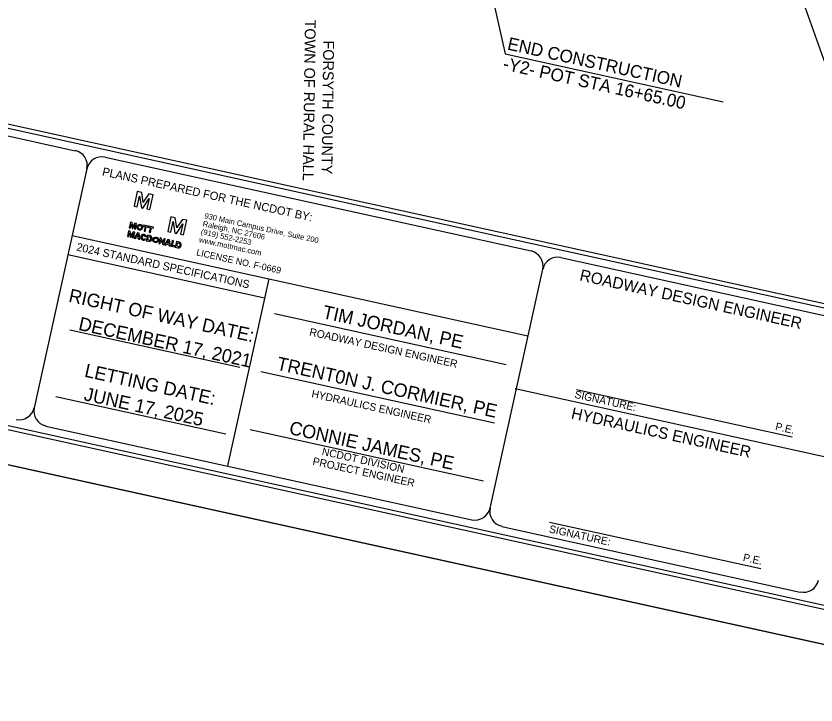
# Model space of a CAD drawing. Extents: x 1609449 to 1623942, y 894240 to 902860.
# Drawn here: x 1618272 to 1621409, y 894240 to 896944 of the extents above; entities that cross this region are included whole.
import ezdxf

# ---------------------------------------------------------------- set-up
doc = ezdxf.new("R2010")
doc.units = 0
for name, color, linetype in [('Old_Level_2', 7, 'Continuous'), ('Prop Horizontal Alignment Station Label', 7, 'Continuous'), ('Scratch_Level_0', 7, 'Continuous'), ('Scratch_Level_1', 7, 'Continuous'), ('Sheet Cutting Line CELL', 7, 'Continuous'), ('Sheet Data Field CELL', 7, 'Continuous'), ('Sheet Plot Border Inside CELL', 7, 'Continuous'), ('Sheet Plot Border Outside CELL', 7, 'Continuous'), ('Sheet Title CELL', 7, 'Continuous')]:
    doc.layers.add(name, color=color, linetype=linetype)

msp = doc.modelspace()

# ---------------------------------------------------------------- linework, layer by layer
at = {"layer": 'Old_Level_2'}
for p, q in [((1618747.5, 896255.9), (1618734.8, 896198.2)), ((1618764.6, 896252.1), (1618747.5, 896255.9)), ((1618770.7, 896213.4), (1618764.6, 896252.1)), ((1618746.9, 896195.5), (1618756.1, 896237)), ((1618756.1, 896237), (1618756.2, 896237)), ((1618756.2, 896237), (1618763.3, 896191.9)), ((1618768.6, 896190.8), (1618794, 896228.8)), ((1618792.8, 896245.9), (1618771, 896213.4)), ((1618794.2, 896228.8), (1618785, 896187.2)), ((1618809.9, 896242.1), (1618792.8, 896245.9)), ((1618794, 896228.8), (1618794.2, 896228.8)), ((1618797.2, 896184.5), (1618809.9, 896242.1)), ((1618734.8, 896198.2), (1618746.9, 896195.5)), ((1618763.3, 896191.9), (1618768.6, 896190.8)), ((1618770.5, 896212.9), (1618770.7, 896213.4)), ((1618770.9, 896212.8), (1618770.5, 896212.9)), ((1618771, 896213.4), (1618770.9, 896212.8)), ((1618785, 896187.2), (1618797.2, 896184.5)), ((1618879.3, 896156.4), (1618866.6, 896098.7)), ((1618896.4, 896152.6), (1618879.3, 896156.4)), ((1618720.9, 896135.1), (1618716, 896113)), ((1618720.6, 896112), (1618724.1, 896127.9)), ((1618727.4, 896133.7), (1618720.9, 896135.1)), ((1618724.1, 896127.9), (1618724.3, 896127.9)), ((1618724.1, 896127.9), (1618724.3, 896127.9)), ((1618724.3, 896127.9), (1618726.9, 896110.6)), ((1618729.8, 896118.7), (1618727.4, 896133.7)), ((1618729.1, 896110.2), (1618738.7, 896124.7)), ((1618738.3, 896131.2), (1618729.8, 896118.7)), ((1618738.9, 896124.6), (1618735.4, 896108.8)), ((1618744.8, 896129.8), (1618738.3, 896131.2)), ((1618738.7, 896124.7), (1618738.9, 896124.6)), ((1618738.7, 896124.7), (1618738.9, 896124.6)), ((1618738.7, 896124.7), (1618738.9, 896124.6)), ((1618740, 896107.8), (1618744.8, 896129.8)), ((1618740, 896107.8), (1618744.8, 896129.8)), ((1618878.8, 896096), (1618887.9, 896137.5)), ((1618887.9, 896137.5), (1618888.1, 896137.5)), ((1618888.1, 896137.5), (1618895.2, 896092.4)), ((1618902.5, 896113.9), (1618896.4, 896152.6)), ((1618900.5, 896091.3), (1618925.9, 896129.3)), ((1618924.6, 896146.4), (1618902.9, 896113.9)), ((1618926, 896129.3), (1618916.9, 896087.7)), ((1618941.7, 896142.6), (1618924.6, 896146.4)), ((1618925.9, 896129.3), (1618926, 896129.3)), ((1618929, 896085), (1618941.7, 896142.6)), ((1618713.3, 896100.9), (1618708.5, 896078.8)), ((1618713, 896077.8), (1618716.5, 896093.7)), ((1618719.8, 896099.4), (1618713.3, 896100.9)), ((1618716, 896113), (1618720.6, 896112)), ((1618716.5, 896093.7), (1618716.7, 896093.7)), ((1618716.7, 896093.7), (1618719.4, 896076.4)), ((1618722.3, 896084.5), (1618719.8, 896099.4)), ((1618721.5, 896076), (1618731.2, 896090.5)), ((1618730.8, 896097), (1618722.3, 896084.5)), ((1618726.9, 896110.6), (1618729.1, 896110.2)), ((1618731.4, 896090.4), (1618727.9, 896074.6)), ((1618737.3, 896095.6), (1618730.8, 896097)), ((1618731.2, 896090.5), (1618731.4, 896090.4)), ((1618732.5, 896073.6), (1618737.3, 896095.6)), ((1618735.4, 896108.8), (1618740, 896107.8)), ((1618866.6, 896098.7), (1618878.8, 896096)), ((1618895.2, 896092.4), (1618900.5, 896091.3)), ((1618902.4, 896113.4), (1618902.5, 896113.9)), ((1618902.7, 896113.3), (1618902.4, 896113.4)), ((1618902.9, 896113.9), (1618902.7, 896113.3)), ((1618708.5, 896078.8), (1618713, 896077.8)), ((1618719.4, 896076.4), (1618721.5, 896076)), ((1618727.9, 896074.6), (1618732.5, 896073.6)), ((1618779.8, 896067.9), (1618776.3, 896070.6)), ((1618779.8, 896067.9), (1618776.3, 896070.6)), ((1618778.7, 896078.9), (1618783, 896079.9)), ((1618778.7, 896078.9), (1618783, 896079.9)), ((1618784.7, 896073.2), (1618782.3, 896062.6)), ((1618782.3, 896062.6), (1618792.4, 896060.3)), ((1618787.2, 896084.6), (1618784.7, 896073.2)), ((1618797.3, 896082.4), (1618787.2, 896084.6)), ((1618787.9, 896065.8), (1618790.9, 896079.5)), ((1618793.3, 896064.6), (1618787.9, 896065.8)), ((1618790.9, 896079.5), (1618796.4, 896078.3)), ((1618901.3, 896059.5), (1618898.8, 896048)), ((1618901.3, 896059.5), (1618901.3, 896059.5)), ((1618911.4, 896057.2), (1618901.3, 896059.5)), ((1618916.9, 896087.7), (1618929, 896085)), ((1618898.8, 896048), (1618896.5, 896037.4)), ((1618896.5, 896037.4), (1618906.5, 896035.2)), ((1618902, 896040.6), (1618905, 896054.4)), ((1618907.4, 896039.4), (1618902, 896040.6)), ((1618905, 896054.4), (1618910.5, 896053.2)), ((1618910.4, 896053), (1618910.4, 896053))]:
    msp.add_line(p, q, dxfattribs=at)
for points in [[(1618771.6, 896119.7), (1618778, 896118.3), (1618774, 896100.3), (1618778.8, 896099.2), (1618782.7, 896117.2), (1618789.1, 896115.8), (1618790, 896119.9), (1618772.5, 896123.7), (1618771.6, 896119.7)], [(1618735.1, 896073), (1618740.4, 896071.8), (1618742.6, 896075.2), (1618752.1, 896073.1), (1618752.7, 896069.1), (1618757.8, 896068), (1618754.2, 896091.9), (1618748.4, 896093.1), (1618735.1, 896073)], [(1618791.9, 896115.2), (1618798.3, 896113.8), (1618794.3, 896095.8), (1618799.1, 896094.8), (1618803, 896112.7), (1618809.4, 896111.3), (1618810.3, 896115.4), (1618792.8, 896119.2), (1618791.9, 896115.2)], [(1618744.7, 896079), (1618750.4, 896087.7), (1618751.8, 896077.4), (1618744.7, 896079)], [(1618839.5, 896065), (1618839.6, 896064.9), (1618847.1, 896048.3), (1618851.5, 896047.3), (1618856.3, 896069.4), (1618851.8, 896070.4), (1618848.7, 896056.4), (1618841.3, 896072.7), (1618836.8, 896073.7), (1618831.9, 896051.6), (1618836.3, 896050.7), (1618839.5, 896065)], [(1618854.3, 896046.7), (1618859.6, 896045.5), (1618861.8, 896048.9), (1618871.3, 896046.8), (1618871.9, 896042.8), (1618877.1, 896041.7), (1618873.4, 896065.6), (1618867.6, 896066.9), (1618854.3, 896046.7)], [(1618863.9, 896052.7), (1618869.6, 896061.5), (1618871, 896051.2), (1618863.9, 896052.7)], [(1618893.8, 896038), (1618894.7, 896041.9), (1618885.1, 896044), (1618889.1, 896062.1), (1618884.6, 896063.2), (1618879.7, 896041.1), (1618893.8, 896038)], [(1618893.8, 896038), (1618894.7, 896041.9), (1618885.1, 896044), (1618889.1, 896062.1), (1618884.6, 896063.2), (1618879.7, 896041.1), (1618893.8, 896038), (1618894.7, 896041.9)]]:
    msp.add_lwpolyline(points, dxfattribs=at)
msp.add_arc((1618908.9, 896046.2), 11.3, 257.5755, 77.5755, dxfattribs=at)
for centre, major_axis, ratio in [((1618757.4, 896115.5), (2.4, 11), 0.993118), ((1618757.4, 896115.5), (1.59, 7.18), 0.916103), ((1618819.5, 896065.9), (2.4, 11), 0.993118), ((1618819.5, 896065.9), (1.59, 7.18), 0.916103)]:
    msp.add_ellipse(centre, major_axis=major_axis, ratio=ratio, dxfattribs=at)
for centre, major_axis, ratio, start_param, end_param in [((1618772.3, 896076.3), (2.4, 11), 0.993118, 5.246647, 10.366427), ((1618772.3, 896076.3), (2.4, 11), 0.993118, 5.246647, 10.366427), ((1618772.3, 896076.3), (1.59, 7.18), 0.916103, 5.276876, 10.296021), ((1618772.3, 896076.3), (1.59, 7.18), 0.916103, 5.276876, 9.424778), ((1618772.3, 896076.3), (1.59, 7.18), 0.916103, 3.141593, 4.012835), ((1618794.8, 896071.4), (-2.4, -11), 0.930276, 0, 3.141593), ((1618794.9, 896071.4), (-1.52, -6.88), 0.900832, 0, 3.141593), ((1618909, 896046.3), (-1.52, -6.88), 0.900832, 0, 3.141593)]:
    msp.add_ellipse(centre, major_axis=major_axis, ratio=ratio, start_param=start_param, end_param=end_param, dxfattribs=at)
at = {"layer": 'Prop Horizontal Alignment Station Label'}
for p, q in [((1619929.3, 897951.2), (1620189.9, 896796.1)), ((1621087, 897764.3), (1621535, 896499.9)), ((1620189.9, 896796.1), (1621044.1, 896607.9))]:
    msp.add_line(p, q, dxfattribs=at)
at = {"layer": 'Scratch_Level_0'}
msp.add_lwpolyline([(1615937.3, 900755.3), (1622890.3, 899223.5), (1622107.1, 895668.6), (1615154.1, 897200.4)], close=True, dxfattribs=at)
at = {"layer": 'Scratch_Level_1'}
msp.add_lwpolyline([(1615937.3, 900755.3), (1622890.3, 899223.5), (1622107.1, 895668.6), (1615154.1, 897200.4)], close=True, dxfattribs=at)
at = {"layer": 'Sheet Cutting Line CELL'}
msp.add_line((1612654.8, 896414.4), (1622522.2, 894240.5), dxfattribs=at)
at = {"layer": 'Sheet Plot Border Inside CELL'}
msp.add_lwpolyline([(1612759.9, 896529.1), (1622524.8, 894377.7), (1623886.8, 900560.1), (1614122, 902711.4)], close=True, dxfattribs=at)
at = {"layer": 'Sheet Plot Border Outside CELL'}
msp.add_lwpolyline([(1623942.2, 900685.8), (1614074.8, 902859.7), (1612654.8, 896414.4), (1622522.2, 894240.5)], close=True, dxfattribs=at)
at = {"layer": 'Sheet Title CELL'}
for p, q in [((1614291.7, 897374.7), (1622612.2, 895541.6)), ((1616277.5, 896906.4), (1618504.1, 896415.8)), ((1618621.3, 896390.1), (1620291.3, 896022.2)), ((1618549.8, 896344.4), (1618343.3, 895406.9)), ((1620279.2, 895688.4), (1618492, 896082.2)), ((1619246.4, 895837.6), (1618475.6, 896007.5)), ((1620408.5, 895996.4), (1621579, 895738.5)), ((1620130.4, 895013.1), (1620336.9, 895950.6)), ((1619262.9, 895912.4), (1619101.2, 895178.5)), ((1619024.3, 895886.6), (1619024.3, 895886.6)), ((1619285, 895776.9), (1620194.1, 895576.5)), ((1619149.5, 895565), (1618482.9, 895711.9)), ((1618816, 895638.4), (1618816, 895638.4)), ((1619232, 895549.8), (1620147.5, 895348.1)), ((1620228.4, 895483.2), (1621521.4, 895198.3)), ((1620469.3, 895479.2), (1621314.5, 895293)), ((1619094.2, 895303.2), (1618427.7, 895450)), ((1619189.6, 895321.3), (1620105.1, 895119.6)), ((1620363.4, 894958.4), (1621192.5, 894775.7))]:
    msp.add_line(p, q, dxfattribs=at)
for points in [[(1613724.2, 896332.3), (1622396.2, 894421.7)], [(1618388.9, 895335.4), (1620058.9, 894967.4)], [(1620176.1, 894941.6), (1621346.7, 894683.8)]]:
    msp.add_lwpolyline(points, dxfattribs=at)
for centre, start, end in [((1618491.3, 896357.6), 347.5755, 77.5755), ((1618608.5, 896331.7), 77.5755, 167.5755), ((1620278.4, 895963.8), 347.5755, 77.5755), ((1620395.6, 895938), 77.5755, 167.5755), ((1618284.7, 895420), 257.5755, 347.5755), ((1618401.9, 895394.2), 167.5755, 257.5755), ((1620071.9, 895026.3), 257.5755, 347.5755), ((1620189.1, 895000.5), 167.5755, 257.5755), ((1621359.6, 894742.7), 257.5755, 347.5755)]:
    msp.add_arc(centre, 60, start, end, dxfattribs=at)

# ---------------------------------------------------------------- texts
at = {"layer": 'Old_Level_2'}
for s, p in [('930 Main Campus Drive, Suite 200', (1619009.1, 896151.1)), ('Raleigh, NC 27606', (1619002.2, 896119.8)), ('(919) 552-2253', (1618995.3, 896088.5)), ('www.mottmac.com', (1618988.4, 896057.1))]:
    msp.add_text(s, height=21.375, rotation=347.5755, dxfattribs=at).set_placement(p)
at = {"layer": 'Prop Horizontal Alignment Station Label'}
for s, height, rotation, p in [('TOWN OF RURAL HALL', 42.35, 269.2147, (1619404.9, 896930.7)), ('FORSYTH COUNTY', 42.35, 269.2147, (1619476.9, 896848.6)), ('END CONSTRUCTION', 50, 347.5755, (1620195.5, 896813.1)), ('-Y2- POT STA 16+65.00', 50, 347.5755, (1620178.2, 896735))]:
    msp.add_text(s, height=height, rotation=rotation, dxfattribs=at).set_placement(p)
at = {"layer": 'Sheet Data Field CELL'}
for s, p in [('TIM JORDAN, PE', (1619470.5, 895759.3)), ('DECEMBER 17, 2021', (1618513.9, 895712.9)), ('TRENT0N J. CORMIER, PE', (1619290.6, 895556.8)), ('JUNE 17, 2025', (1618535.3, 895436.7)), ('CONNIE JAMES, PE', (1619339.7, 895304.5))]:
    msp.add_text(s, height=52.501, rotation=347.5755, dxfattribs=at).set_placement(p)
at = {"layer": 'Sheet Title CELL'}
for s, height, rotation, p in [('PLANS PREPARED FOR THE NCDOT BY:', 32.397, 347.5755, (1618607.8, 896319.4)), ('2024 STANDARD SPECIFICATIONS', 31.2, 347.5755, (1618506.8, 896024.2)), ('LICENSE NO. F-0669', 25.943, 347.5606, (1618977, 896005.4)), ('ROADWAY DESIGN ENGINEER', 44.996, 347.5755, (1620479.2, 895907.1)), ('RIGHT OF WAY DATE: ', 52.499, 347.5755, (1618475.3, 895823.5)), ('ROADWAY DESIGN ENGINEER', 29.997, 347.5755, (1619420.3, 895691.2)), ('LETTING DATE:', 52.499, 347.5755, (1618537.4, 895529.4)), ('HYDRAULICS ENGINEER', 29.997, 347.5755, (1619428.4, 895448.5)), ('SIGNATURE:', 30, 347.5755, (1620460.3, 895446.2)), (' HYDRAULICS ENGINEER', 45, 347.5755, (1620429.6, 895368.7)), ('P.E.', 30, 347.5755, (1621247.1, 895320.4)), ('NCDOT DIVISION ', 29.997, 347.5755, (1619469.2, 895222.1)), ('PROJECT ENGINEER', 29.997, 347.5755, (1619433.1, 895184)), ('SIGNATURE:', 30, 347.5755, (1620360, 894918)), ('P.E.', 30, 347.5755, (1621120.3, 894806.4))]:
    msp.add_text(s, height=height, rotation=rotation, dxfattribs=at).set_placement(p)

doc.saveas('drawing.dxf')
